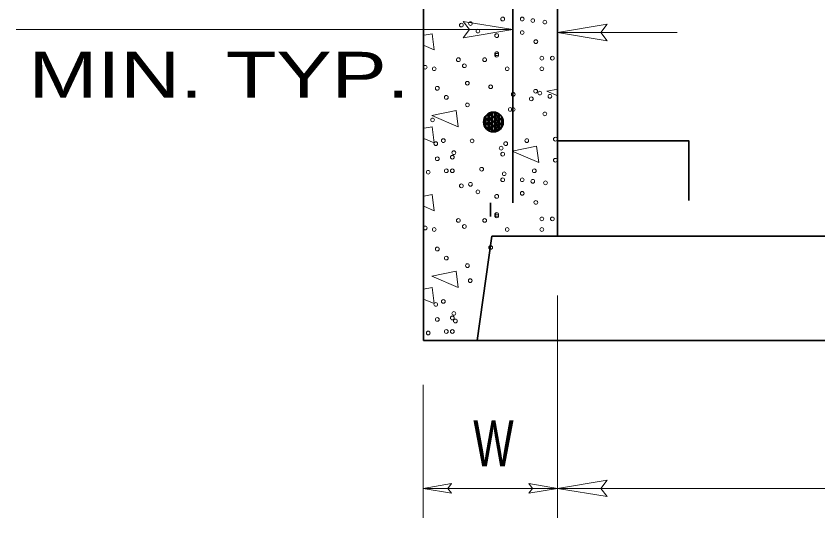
# Model space of a CAD drawing. Extents: x 5.1 to 20.2, y -16.7 to 4.3.
# Drawn here: x 8.925 to 11.185, y -5.238 to -3.824 of the extents above; entities that cross this region are included whole.
import ezdxf
from ezdxf.enums import TextEntityAlignment as Align

# ---------------------------------------------------------------- set-up
doc = ezdxf.new("R2010")
doc.units = 0
doc.header["$LTSCALE"] = 0.052
for name, color, linetype, lineweight in [('1', 7, 'Continuous', 35), ('10', 7, 'Continuous', 13), ('12', 7, 'Continuous', 53), ('13', 7, 'Continuous', 25), ('6', 7, 'Continuous', 13)]:
    doc.layers.add(name, color=color, linetype=linetype, lineweight=lineweight)

msp = doc.modelspace()

# ---------------------------------------------------------------- linework, layer by layer
at = {"layer": '1'}
for p, q in [((10.45017, -4.44358), (10.45017, -2.96833)), ((10.07242, -4.73767), (10.07242, -3.23933)), ((10.32492, -4.35042), (10.32492, -3.298)), ((10.26025, -4.10475), (10.24217, -4.12275)), ((10.25367, -4.11125), (10.24217, -4.12275)), ((10.26325, -4.1275), (10.24533, -4.1095)), ((10.25675, -4.121), (10.24533, -4.1095)), ((10.25025, -4.11442), (10.24533, -4.1095)), ((10.26675, -4.11125), (10.24575, -4.13208)), ((10.26675, -4.09825), (10.24583, -4.119)), ((10.26383, -4.12658), (10.24583, -4.10842)), ((10.25733, -4.12), (10.24583, -4.10842)), ((10.25083, -4.11342), (10.24583, -4.10842)), ((10.24617, -4.13075), (10.24625, -4.10783)), ((10.24617, -4.12158), (10.24625, -4.10783)), ((10.24617, -4.13683), (10.24625, -4.11042)), ((10.24625, -4.11233), (10.24625, -4.10783)), ((10.24875, -4.13083), (10.24883, -4.10425)), ((10.24875, -4.14), (10.24883, -4.11042)), ((10.24883, -4.12158), (10.24883, -4.10425)), ((10.24883, -4.11233), (10.24883, -4.10425)), ((10.26967, -4.13408), (10.24883, -4.11308)), ((10.27033, -4.13308), (10.2495, -4.11217)), ((10.26967, -4.121), (10.25083, -4.10208)), ((10.26325, -4.1145), (10.25083, -4.10208)), ((10.25675, -4.10792), (10.25083, -4.10208)), ((10.27042, -4.12), (10.25175, -4.10133)), ((10.26392, -4.1135), (10.25175, -4.10133)), ((10.25742, -4.10692), (10.25175, -4.10133)), ((10.27042, -4.09467), (10.25225, -4.1125)), ((10.27325, -4.10475), (10.25225, -4.12558)), ((10.25533, -4.14), (10.25542, -4.1105)), ((10.25542, -4.12158), (10.2555, -4.09867)), ((10.25542, -4.11242), (10.2555, -4.09867)), ((10.25542, -4.13083), (10.2555, -4.10125)), ((10.27617, -4.12758), (10.25542, -4.10667)), ((10.2555, -4.10317), (10.2555, -4.09867)), ((10.27692, -4.12658), (10.25608, -4.10567)), ((10.258, -4.12158), (10.25808, -4.09717)), ((10.258, -4.13083), (10.25808, -4.10125)), ((10.258, -4.14), (10.25808, -4.1105)), ((10.25808, -4.11242), (10.25808, -4.09717)), ((10.25808, -4.10317), (10.25808, -4.09717)), ((10.27625, -4.1145), (10.25875, -4.097)), ((10.26975, -4.108), (10.25875, -4.097)), ((10.26333, -4.10142), (10.25875, -4.097)), ((10.27975, -4.11133), (10.25875, -4.13217)), ((10.27042, -4.09467), (10.25883, -4.106)), ((10.27983, -4.09825), (10.25883, -4.11908)), ((10.27692, -4.1135), (10.25992, -4.09642)), ((10.27042, -4.107), (10.25992, -4.09642)), ((10.26392, -4.1005), (10.25992, -4.09642)), ((10.28275, -4.12108), (10.26192, -4.10017)), ((10.28267, -4.13408), (10.26192, -4.11308)), ((10.28342, -4.13317), (10.2625, -4.11217)), ((10.28342, -4.12008), (10.26258, -4.09917)), ((10.26458, -4.12167), (10.26467, -4.09508)), ((10.26458, -4.13083), (10.26467, -4.10125)), ((10.26458, -4.14008), (10.26467, -4.1105)), ((10.26467, -4.11242), (10.26467, -4.09508)), ((10.26467, -4.10325), (10.26467, -4.09508)), ((10.28117, -4.097), (10.26533, -4.11258)), ((10.28625, -4.10483), (10.26533, -4.12567)), ((10.26717, -4.13083), (10.26733, -4.10133)), ((10.26717, -4.14008), (10.26725, -4.1105)), ((10.26725, -4.12167), (10.26733, -4.09467)), ((10.26725, -4.11242), (10.26733, -4.09467)), ((10.26725, -4.10325), (10.26733, -4.09467)), ((10.28925, -4.12758), (10.26842, -4.10667)), ((10.28992, -4.12658), (10.26908, -4.10567)), ((10.28925, -4.11458), (10.2695, -4.09467)), ((10.28275, -4.108), (10.2695, -4.09467)), ((10.27625, -4.1015), (10.2695, -4.09467)), ((10.26975, -4.09492), (10.2695, -4.09467)), ((10.29, -4.11358), (10.27108, -4.09467)), ((10.2835, -4.107), (10.27108, -4.09467)), ((10.277, -4.10058), (10.27108, -4.09467)), ((10.28892, -4.10217), (10.27183, -4.11908)), ((10.29275, -4.11133), (10.27183, -4.13217)), ((10.27375, -4.14008), (10.27383, -4.1105)), ((10.27383, -4.12167), (10.27392, -4.09492)), ((10.27383, -4.11242), (10.27392, -4.09492)), ((10.27383, -4.13083), (10.27392, -4.10133)), ((10.27392, -4.10325), (10.27392, -4.09492)), ((10.29575, -4.12108), (10.275, -4.10017)), ((10.29642, -4.12008), (10.27558, -4.09917)), ((10.29583, -4.13258), (10.27558, -4.11225)), ((10.27642, -4.12167), (10.2765, -4.09542)), ((10.27642, -4.13092), (10.2765, -4.10133)), ((10.27642, -4.14008), (10.2765, -4.1105)), ((10.2765, -4.11242), (10.2765, -4.09542)), ((10.2765, -4.10325), (10.2765, -4.09542)), ((10.29458, -4.1095), (10.27833, -4.12567)), ((10.29767, -4.123), (10.28142, -4.10675)), ((10.29767, -4.12142), (10.28208, -4.10575)), ((10.283, -4.13092), (10.28308, -4.10133)), ((10.283, -4.14008), (10.28308, -4.11058)), ((10.28308, -4.12167), (10.28308, -4.098)), ((10.28308, -4.1125), (10.28308, -4.098)), ((10.28308, -4.10325), (10.28308, -4.098)), ((10.28558, -4.14008), (10.28567, -4.11058)), ((10.28567, -4.12167), (10.28575, -4.0995)), ((10.28567, -4.1125), (10.28575, -4.0995)), ((10.28567, -4.13092), (10.28575, -4.10133)), ((10.28575, -4.10325), (10.28575, -4.0995)), ((10.29767, -4.12142), (10.28858, -4.11225)), ((10.29217, -4.13908), (10.29225, -4.11058)), ((10.29225, -4.13092), (10.29233, -4.10592)), ((10.29225, -4.12175), (10.29233, -4.10592)), ((10.29225, -4.1125), (10.29233, -4.10592)), ((10.29483, -4.13092), (10.29492, -4.11017)), ((10.29483, -4.12175), (10.29492, -4.11017)), ((10.29483, -4.13492), (10.29492, -4.11058)), ((10.29492, -4.1125), (10.29492, -4.11017)), ((10.24717, -4.11767), (10.24217, -4.12275)), ((10.26317, -4.1405), (10.24225, -4.11958)), ((10.25667, -4.13408), (10.24225, -4.11958)), ((10.25017, -4.1275), (10.24225, -4.11958)), ((10.24367, -4.12092), (10.24225, -4.11958)), ((10.25733, -4.13308), (10.24242, -4.118)), ((10.25075, -4.1265), (10.24242, -4.118)), ((10.24433, -4.11992), (10.24242, -4.118)), ((10.26383, -4.13958), (10.243, -4.11867)), ((10.25942, -4.14817), (10.24408, -4.13275)), ((10.25725, -4.14608), (10.24408, -4.13275)), ((10.25075, -4.13958), (10.24408, -4.13275)), ((10.24433, -4.133), (10.24408, -4.13275)), ((10.26017, -4.11767), (10.24442, -4.1335)), ((10.25367, -4.12425), (10.24442, -4.1335)), ((10.24708, -4.13075), (10.24442, -4.1335)), ((10.24617, -4.13683), (10.24617, -4.11967)), ((10.24617, -4.13683), (10.24617, -4.12883)), ((10.24875, -4.1405), (10.24883, -4.11967)), ((10.24875, -4.1405), (10.24875, -4.12892)), ((10.26958, -4.14708), (10.24883, -4.12608)), ((10.26667, -4.12425), (10.2495, -4.14133)), ((10.27033, -4.14617), (10.2495, -4.12508)), ((10.26017, -4.13075), (10.2495, -4.14133)), ((10.27325, -4.11775), (10.25225, -4.13867)), ((10.27617, -4.14058), (10.25533, -4.11958)), ((10.25533, -4.14608), (10.25542, -4.11967)), ((10.25533, -4.14608), (10.25542, -4.12892)), ((10.27267, -4.15017), (10.25533, -4.13267)), ((10.27683, -4.13967), (10.256, -4.11867)), ((10.27408, -4.14992), (10.256, -4.13167)), ((10.27317, -4.13083), (10.25683, -4.147)), ((10.25792, -4.14758), (10.258, -4.11967)), ((10.25792, -4.14758), (10.258, -4.12892)), ((10.27975, -4.12425), (10.25875, -4.14517)), ((10.28267, -4.14708), (10.26183, -4.12617)), ((10.28333, -4.14617), (10.2625, -4.12517)), ((10.2645, -4.14925), (10.26467, -4.11975)), ((10.2645, -4.14975), (10.26458, -4.12892)), ((10.28617, -4.11775), (10.26525, -4.13867)), ((10.28617, -4.13083), (10.26683, -4.15008)), ((10.26717, -4.14925), (10.26725, -4.11975)), ((10.26717, -4.15008), (10.26725, -4.12892)), ((10.28275, -4.14717), (10.26833, -4.13267)), ((10.28917, -4.14058), (10.26842, -4.11967)), ((10.28992, -4.13967), (10.269, -4.11875)), ((10.28375, -4.14658), (10.269, -4.13167)), ((10.29275, -4.12433), (10.27175, -4.14525)), ((10.27375, -4.14933), (10.27383, -4.11975)), ((10.27375, -4.15), (10.27383, -4.12892)), ((10.29533, -4.13375), (10.27492, -4.11317)), ((10.29017, -4.14158), (10.27492, -4.12617)), ((10.29092, -4.14067), (10.2755, -4.12517)), ((10.27633, -4.14933), (10.27642, -4.11975)), ((10.27633, -4.1495), (10.27642, -4.129)), ((10.29758, -4.1195), (10.27833, -4.13875)), ((10.29533, -4.13375), (10.28133, -4.11967)), ((10.29583, -4.13258), (10.28208, -4.11875)), ((10.283, -4.147), (10.28308, -4.11975)), ((10.283, -4.147), (10.283, -4.129)), ((10.2945, -4.13558), (10.283, -4.14708)), ((10.29758, -4.1195), (10.28483, -4.13225)), ((10.2945, -4.13558), (10.28483, -4.14525)), ((10.28558, -4.14542), (10.28567, -4.11975)), ((10.28558, -4.14542), (10.28567, -4.129)), ((10.29767, -4.123), (10.28792, -4.11317)), ((10.2945, -4.13558), (10.29133, -4.13875)), ((10.29217, -4.13908), (10.29225, -4.11983)), ((10.29217, -4.13908), (10.29225, -4.129)), ((10.29483, -4.13492), (10.29483, -4.11983)), ((10.29483, -4.13492), (10.29483, -4.129)), ((10.25633, -4.14675), (10.2455, -4.13583)), ((10.25633, -4.14675), (10.2455, -4.13583)), ((10.25017, -4.1405), (10.2455, -4.13583)), ((10.25633, -4.14675), (10.24875, -4.13917)), ((10.25942, -4.14817), (10.24942, -4.13817)), ((10.25358, -4.13725), (10.2495, -4.14133)), ((10.25633, -4.14675), (10.25525, -4.14567)), ((10.25942, -4.14817), (10.25592, -4.14475)), ((10.26667, -4.13733), (10.25683, -4.147)), ((10.26008, -4.14383), (10.25683, -4.147)), ((10.27267, -4.15017), (10.26183, -4.13917)), ((10.27408, -4.14992), (10.26242, -4.13817)), ((10.27967, -4.13733), (10.26683, -4.15008)), ((10.27317, -4.14383), (10.26683, -4.15008)), ((10.29267, -4.13742), (10.283, -4.14708)), ((10.28608, -4.14392), (10.283, -4.14708)), ((10.26133, -4.35042), (10.26133, -4.38867)), ((10.22392, -4.73767), (10.265, -4.44358)), ((10.265, -4.44358), (14.39283, -4.44358)), ((10.07242, -4.73767), (14.62242, -4.73767))]:
    msp.add_line(p, q, dxfattribs=at)
msp.add_lwpolyline([(10.45017, -4.17567), (10.82075, -4.17567), (10.82075, -4.3435)], dxfattribs=at)
msp.add_circle((10.26994, -4.12243), 0.02789, dxfattribs=at)
at = {"layer": '10'}
for p, q in [((10.18492, -3.83892), (10.32492, -3.86225)), ((10.18492, -3.83892), (10.20242, -3.86225)), ((10.32492, -3.86225), (8.92458, -3.86225)), ((10.18492, -3.88558), (10.32492, -3.86225)), ((10.18492, -3.88558), (10.20242, -3.86225)), ((10.5905, -3.84692), (10.4505, -3.87025)), ((10.5905, -3.84692), (10.573, -3.87025)), ((10.4505, -3.87025), (10.78775, -3.87025)), ((10.5905, -3.89358), (10.4505, -3.87025)), ((10.5905, -3.89358), (10.573, -3.87025)), ((10.45017, -4.61083), (10.45017, -5.23767)), ((10.07183, -4.86267), (10.07183, -5.23767)), ((10.15183, -5.141), (10.07183, -5.15433)), ((10.15183, -5.141), (10.14183, -5.15433)), ((10.37017, -5.141), (10.45017, -5.15433)), ((10.37017, -5.141), (10.38017, -5.15433)), ((10.59017, -5.131), (10.45017, -5.15433)), ((10.59017, -5.131), (10.57267, -5.15433)), ((10.15183, -5.16767), (10.07183, -5.15433)), ((10.45017, -5.15433), (10.07183, -5.15433)), ((10.15183, -5.16767), (10.14183, -5.15433)), ((10.37017, -5.16767), (10.45017, -5.15433)), ((10.37017, -5.16767), (10.38017, -5.15433)), ((10.59017, -5.17767), (10.45017, -5.15433)), ((10.59017, -5.17767), (10.57267, -5.15433))]:
    msp.add_line(p, q, dxfattribs=at)
msp.add_lwpolyline([(14.62242, -5.15433), (14.24408, -5.15433), (10.45017, -5.15433)], dxfattribs=at)
at = {"layer": '6'}
for p, q in [((10.42025, -4.03575), (10.45142, -4.02958)), ((10.45133, -4.049), (10.42025, -4.03575))]:
    msp.add_line(p, q, dxfattribs=at)
for points in [[(10.07517, -3.87808), (10.09708, -3.87383), (10.10308, -3.91942), (10.07508, -3.90733)], [(10.07433, -4.14017), (10.09708, -4.13575), (10.10308, -4.18133), (10.07425, -4.16892)], [(10.07375, -4.33117), (10.09708, -4.32658), (10.10308, -4.37217), (10.07367, -4.3595)], [(10.07292, -4.59317), (10.09708, -4.5885), (10.10308, -4.63408), (10.07283, -4.62108)]]:
    msp.add_lwpolyline(points, dxfattribs=at)
for points in [[(10.096, -4.10367), (10.16492, -4.09017), (10.17092, -4.13575)], [(10.32275, -4.20442), (10.39167, -4.19092), (10.39767, -4.2365)], [(10.096, -4.55642), (10.16492, -4.54292), (10.17092, -4.5885)]]:
    msp.add_lwpolyline(points, close=True, dxfattribs=at)
for centre in [(10.20508, -3.84517), (10.29608, -3.83242), (10.35125, -3.83242), (10.38092, -3.83667), (10.41487, -3.84092), (10.17958, -3.84942), (10.22625, -3.86633), (10.27917, -3.87908), (10.35125, -3.87058), (10.38942, -3.89608), (10.27917, -3.93), (10.27917, -3.93425), (10.17117, -3.94692), (10.24525, -3.94692), (10.40633, -3.94267), (10.43608, -3.94267), (10.07783, -3.96817), (10.10325, -3.97242), (10.18808, -3.96392), (10.30883, -3.97242), (10.40633, -3.97242), (10.11175, -4.0275), (10.19644, -4.01331), (10.26217, -4.02325), (10.32575, -4.0445), (10.38892, -4.03583), (10.40067, -4.04092), (10.42908, -4.05), (10.13717, -4.053), (10.37667, -4.05717), (10.19658, -4.07417), (10.31733, -4.08692), (10.32575, -4.08692), (10.09853, -4.11658), (10.41483, -4.09958), (10.1075, -4.18342), (10.12875, -4.17492), (10.20977, -4.17554), (10.30458, -4.18342), (10.36392, -4.17492), (10.4445, -4.17067), (10.29183, -4.19617), (10.11175, -4.22583), (10.15417, -4.22158), (10.15842, -4.20883), (10.29608, -4.21308), (10.4445, -4.23008), (10.08633, -4.264), (10.13717, -4.25975), (10.15417, -4.25975), (10.23675, -4.2555), (10.30033, -4.26825), (10.38517, -4.25975), (10.20508, -4.29792), (10.29608, -4.28517), (10.35125, -4.28517), (10.38092, -4.28942), (10.41675, -4.29367), (10.17958, -4.30217), (10.22625, -4.31908), (10.27917, -4.33183), (10.35125, -4.32333), (10.38942, -4.34883), (10.27917, -4.38275), (10.27917, -4.387), (10.17117, -4.39967), (10.24525, -4.39967), (10.40633, -4.39542), (10.43608, -4.39542), (10.07783, -4.42092), (10.10325, -4.42517), (10.18808, -4.41667), (10.30883, -4.42517), (10.40633, -4.42517), (10.26217, -4.476), (10.11175, -4.48025), (10.13717, -4.50575), (10.19658, -4.52692), (10.20468, -4.56933), (10.1075, -4.63617), (10.12875, -4.62767), (10.11175, -4.67858), (10.15417, -4.67433), (10.15842, -4.66158), (10.16267, -4.68283), (10.08633, -4.71675), (10.13717, -4.7125), (10.15417, -4.7125)]:
    msp.add_circle(centre, 0.00525, dxfattribs=at)

# ---------------------------------------------------------------- texts
at = {"layer": '12', "width": 1.35}
msp.add_text('MIN. TYP.', height=0.129, dxfattribs=at).set_placement((9.49687, -4.05375), align=Align.CENTER)
at = {"layer": '13', "width": 0.7}
msp.add_text('W', height=0.129, dxfattribs=at).set_placement((10.27008, -5.09183), align=Align.CENTER)

doc.saveas('drawing.dxf')
